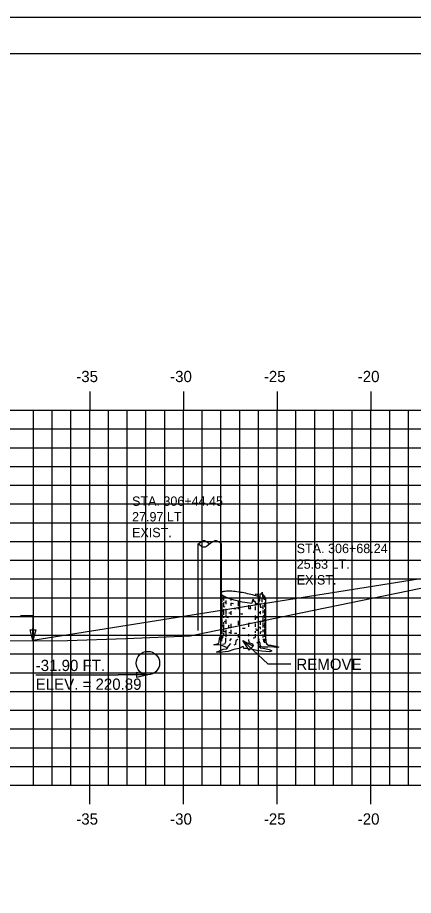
# Model space of a CAD drawing. Extents: x 1137433 to 1137603, y 608981 to 609091.
# Drawn here: x 1137476.8 to 1137497.92, y 609044.46 to 609091.28 of the extents above; entities that cross this region are included whole.
import ezdxf

# ---------------------------------------------------------------- set-up
doc = ezdxf.new("R2010")
doc.units = 0
for name, color, linetype in [('ANNOTATION', 7, 'Continuous'), ('BORDER', 7, 'Continuous'), ('D_Drainage_Culvert', 7, 'Continuous'), ('D_Text_Monospaced', 7, 'Continuous'), ('D_Text_Standard', 7, 'Continuous'), ('H_V ANNOTATION', 7, 'Continuous'), ('MAJOR', 7, 'Continuous'), ('MINOR', 7, 'Continuous'), ('PLOT BOUNDARY', 7, 'Continuous'), ('S_Roadway_Centerline', 7, 'Continuous'), ('S_Trees_Decid_Pay', 7, 'Continuous'), ('S_Utilities_Pole_Power', 7, 'Continuous')]:
    doc.layers.add(name, color=color, linetype=linetype)

msp = doc.modelspace()

# ---------------------------------------------------------------- linework, layer by layer
at = {"layer": 'ANNOTATION'}
for p, q in [((1137498.181, 609061.327), (1137477.623, 609058.046)), ((1137488.823, 609058.049), (1137490.174, 609056.786)), ((1137491.374, 609056.786), (1137490.174, 609056.786))]:
    msp.add_line(p, q, dxfattribs=at)
msp.add_lwpolyline([(1137489.159, 609057.53), (1137488.823, 609058.049), (1137489.364, 609057.749)], close=True, dxfattribs=at)
at = {"layer": 'BORDER'}
msp.add_lwpolyline([(1137440.653, 608984.335), (1137600.653, 608984.335), (1137600.653, 609089.335), (1137440.653, 609089.335)], close=True, dxfattribs=at)
at = {"layer": 'D_Drainage_Culvert'}
msp.add_circle((1137483.753, 609056.85), 0.625, dxfattribs=at)
at = {"layer": 'D_Text_Standard'}
msp.add_line((1137477.771, 609056.225), (1137482.164, 609056.225), dxfattribs=at)
for points in [[(1137477.623, 609058.046), (1137477.633, 609059.372), (1137476.953, 609059.372)], [(1137483.753, 609056.225), (1137482.844, 609056.225), (1137482.164, 609056.225)]]:
    msp.add_lwpolyline(points, dxfattribs=at)
for points in [[(1137477.623, 609058.046), (1137477.482, 609058.629), (1137477.773, 609058.627)], [(1137483.753, 609056.225), (1137483.171, 609056.08), (1137483.171, 609056.371)]]:
    msp.add_lwpolyline(points, close=True, dxfattribs=at)
at = {"layer": 'MAJOR'}
for p, q in [((1137480.653, 609071.337), (1137480.653, 609070.335)), ((1137485.653, 609071.337), (1137485.653, 609070.335)), ((1137490.653, 609071.337), (1137490.653, 609070.335)), ((1137495.653, 609071.337), (1137495.653, 609070.335)), ((1137445.653, 609070.335), (1137585.653, 609070.335)), ((1137445.653, 609070.335), (1137585.653, 609070.335)), ((1137480.653, 609050.335), (1137480.653, 609070.335)), ((1137485.653, 609050.335), (1137485.653, 609070.335)), ((1137490.653, 609050.335), (1137490.653, 609070.335)), ((1137495.653, 609050.335), (1137495.653, 609070.335)), ((1137445.653, 609065.335), (1137585.653, 609065.335)), ((1137445.653, 609060.335), (1137585.653, 609060.335)), ((1137445.653, 609055.335), (1137585.653, 609055.335)), ((1137445.653, 609050.335), (1137585.653, 609050.335)), ((1137445.653, 609050.335), (1137585.653, 609050.335)), ((1137480.653, 609049.333), (1137480.653, 609050.335)), ((1137485.653, 609049.333), (1137485.653, 609050.335)), ((1137490.653, 609049.333), (1137490.653, 609050.335)), ((1137495.653, 609049.333), (1137495.653, 609050.335))]:
    msp.add_line(p, q, dxfattribs=at)
at = {"layer": 'MINOR'}
for p, q in [((1137477.653, 609050.335), (1137477.653, 609070.335)), ((1137478.653, 609050.335), (1137478.653, 609070.335)), ((1137479.653, 609050.335), (1137479.653, 609070.335)), ((1137481.653, 609050.335), (1137481.653, 609070.335)), ((1137482.653, 609050.335), (1137482.653, 609070.335)), ((1137483.653, 609050.335), (1137483.653, 609070.335)), ((1137484.653, 609050.335), (1137484.653, 609070.335)), ((1137486.653, 609050.335), (1137486.653, 609070.335)), ((1137487.653, 609050.335), (1137487.653, 609070.335)), ((1137488.653, 609050.335), (1137488.653, 609070.335)), ((1137489.653, 609050.335), (1137489.653, 609070.335)), ((1137491.653, 609050.335), (1137491.653, 609070.335)), ((1137492.653, 609050.335), (1137492.653, 609070.335)), ((1137493.653, 609050.335), (1137493.653, 609070.335)), ((1137494.653, 609050.335), (1137494.653, 609070.335)), ((1137496.653, 609050.335), (1137496.653, 609070.335)), ((1137497.653, 609050.335), (1137497.653, 609070.335)), ((1137445.653, 609069.335), (1137585.653, 609069.335)), ((1137445.653, 609068.335), (1137585.653, 609068.335)), ((1137445.653, 609067.335), (1137585.653, 609067.335)), ((1137445.653, 609066.335), (1137585.653, 609066.335)), ((1137445.653, 609064.335), (1137585.653, 609064.335)), ((1137445.653, 609063.335), (1137585.653, 609063.335)), ((1137445.653, 609062.335), (1137585.653, 609062.335)), ((1137445.653, 609061.335), (1137585.653, 609061.335)), ((1137445.653, 609059.335), (1137585.653, 609059.335)), ((1137445.653, 609058.335), (1137585.653, 609058.335)), ((1137445.653, 609057.335), (1137585.653, 609057.335)), ((1137445.653, 609056.335), (1137585.653, 609056.335)), ((1137445.653, 609054.335), (1137585.653, 609054.335)), ((1137445.653, 609053.335), (1137585.653, 609053.335)), ((1137445.653, 609052.335), (1137585.653, 609052.335)), ((1137445.653, 609051.335), (1137585.653, 609051.335))]:
    msp.add_line(p, q, dxfattribs=at)
at = {"layer": 'PLOT BOUNDARY'}
msp.add_lwpolyline([(1137432.56, 608981.276), (1137602.56, 608981.276), (1137602.56, 609091.276), (1137432.56, 609091.276)], close=True, dxfattribs=at)
at = {"layer": 'S_Roadway_Centerline'}
msp.add_lwpolyline([(1137445.653, 609057.929), (1137453.384, 609057.836), (1137462.728, 609057.933), (1137472.775, 609058.023), (1137479.462, 609058.055), (1137482.576, 609058.161), (1137486.003, 609058.295), (1137491.397, 609059.425), (1137498.22, 609060.819), (1137499.297, 609060.966), (1137500.585, 609061.068), (1137507.942, 609061.156), (1137511.268, 609061.183), (1137514.305, 609061.154), (1137522.089, 609061.113), (1137524.047, 609060.511), (1137524.139, 609060.485), (1137524.594, 609060.38), (1137530.466, 609059.405), (1137531.069, 609059.477), (1137535.521, 609059.696), (1137539.278, 609059.952)], dxfattribs=at)
at = {"layer": 'S_Trees_Decid_Pay'}
for p, q in [((1137487.699, 609060.482), (1137487.699, 609060.362)), ((1137487.779, 609060.438), (1137487.779, 609060.184)), ((1137487.699, 609060.31), (1137487.699, 609060.096)), ((1137487.699, 609060.051), (1137487.699, 609059.713)), ((1137487.779, 609060.088), (1137487.779, 609059.824)), ((1137487.912, 609060.184), (1137487.912, 609059.993)), ((1137488.184, 609060.271), (1137488.184, 609060.184)), ((1137488.184, 609060.043), (1137488.184, 609059.904)), ((1137488.568, 609060.17), (1137488.568, 609059.89)), ((1137489.113, 609059.933), (1137489.113, 609059.753)), ((1137489.24, 609059.761), (1137489.235, 609059.867)), ((1137489.478, 609060.032), (1137489.478, 609059.913)), ((1137489.478, 609059.861), (1137489.478, 609059.676)), ((1137489.739, 609060.03), (1137489.739, 609059.825)), ((1137489.824, 609060.279), (1137489.824, 609060.104)), ((1137489.888, 609059.933), (1137489.888, 609059.721)), ((1137489.974, 609060.079), (1137489.974, 609059.824)), ((1137487.699, 609059.596), (1137487.699, 609059.235)), ((1137487.779, 609059.727), (1137487.779, 609059.419)), ((1137487.912, 609059.741), (1137487.912, 609059.464)), ((1137487.912, 609059.419), (1137487.912, 609059.31)), ((1137488.184, 609059.618), (1137488.184, 609059.427)), ((1137488.568, 609059.824), (1137488.568, 609059.721)), ((1137489.478, 609059.39), (1137489.478, 609059.161)), ((1137489.739, 609059.618), (1137489.739, 609059.464)), ((1137489.888, 609059.656), (1137489.888, 609059.507)), ((1137489.974, 609059.727), (1137489.974, 609059.258)), ((1137487.699, 609059.198), (1137487.699, 609058.749)), ((1137487.779, 609059.33), (1137487.779, 609059.264)), ((1137487.779, 609059.03), (1137487.779, 609058.932)), ((1137487.912, 609059.175), (1137487.912, 609058.947)), ((1137488.184, 609058.947), (1137488.184, 609058.739)), ((1137488.568, 609059.11), (1137488.568, 609058.889)), ((1137489.113, 609058.975), (1137489.113, 609058.778)), ((1137489.478, 609058.963), (1137489.478, 609058.778)), ((1137489.739, 609059.101), (1137489.739, 609058.881)), ((1137489.888, 609059.33), (1137489.888, 609059.03)), ((1137489.888, 609058.992), (1137489.888, 609058.749)), ((1137489.974, 609059.207), (1137489.974, 609059.073)), ((1137489.974, 609059.015), (1137489.974, 609058.69)), ((1137487.699, 609058.684), (1137487.699, 609058.402)), ((1137487.779, 609058.881), (1137487.779, 609058.521)), ((1137487.779, 609058.469), (1137487.779, 609058.303)), ((1137487.912, 609058.617), (1137487.912, 609058.234)), ((1137488.184, 609058.617), (1137488.184, 609058.418)), ((1137489.478, 609058.543), (1137489.478, 609058.467)), ((1137489.739, 609058.782), (1137489.739, 609058.661)), ((1137489.739, 609058.51), (1137489.739, 609058.411)), ((1137489.888, 609058.638), (1137489.888, 609058.498)), ((1137489.974, 609058.661), (1137489.974, 609058.241)), ((1137488.189, 609058.161), (1137488.109, 609058.029)), ((1137488.568, 609058.389), (1137488.568, 609058.216)), ((1137489.113, 609058.395), (1137489.113, 609058.292)), ((1137489.478, 609058.389), (1137489.478, 609058.216)), ((1137489.888, 609058.366), (1137489.888, 609058.21)), ((1137489.97, 609058.138), (1137489.985, 609058.02))]:
    msp.add_line(p, q, dxfattribs=at)
for points in [[(1137490.024, 609060.353), (1137490.024, 609058.216), (1137490.045, 609058.074), (1137490.05, 609057.948), (1137490.094, 609057.862), (1137490.186, 609057.812), (1137490.322, 609057.812), (1137490.566, 609057.757), (1137490.732, 609057.707), (1137490.59, 609057.677), (1137490.353, 609057.714), (1137490.143, 609057.701), (1137489.882, 609057.707), (1137489.758, 609057.726), (1137489.728, 609057.683), (1137489.665, 609057.726), (1137489.764, 609057.658), (1137489.999, 609057.633), (1137490.23, 609057.572), (1137490.36, 609057.501), (1137490.26, 609057.458), (1137489.839, 609057.477), (1137489.56, 609057.52), (1137489.262, 609057.596), (1137488.976, 609057.633), (1137488.871, 609057.633), (1137488.852, 609057.714), (1137488.784, 609057.72), (1137488.617, 609057.633), (1137488.331, 609057.577), (1137488.033, 609057.47), (1137487.573, 609057.421), (1137487.419, 609057.434), (1137487.761, 609057.584), (1137487.964, 609057.615), (1137487.953, 609057.689), (1137487.693, 609057.788), (1137487.518, 609057.819), (1137487.277, 609057.831), (1137487.475, 609057.868), (1137487.537, 609057.905), (1137487.561, 609057.991), (1137487.573, 609058.161), (1137487.619, 609058.247), (1137487.647, 609058.488), (1137487.647, 609060.574)], [(1137489.646, 609060.392), (1137489.625, 609060.499), (1137489.493, 609060.53), (1137489.485, 609060.442)], [(1137489.668, 609060.026), (1137489.676, 609060.17), (1137489.721, 609060.162), (1137489.735, 609060.537), (1137489.83, 609060.545), (1137489.844, 609060.625), (1137489.882, 609060.287), (1137489.927, 609060.382), (1137489.947, 609060.228), (1137490.024, 609060.353), (1137490.018, 609060.163)], [(1137490.024, 609060.353), (1137489.978, 609060.376), (1137489.956, 609060.442), (1137489.904, 609060.465), (1137489.871, 609060.39)], [(1137489.506, 609060.03), (1137489.47, 609060.133), (1137489.404, 609060.139), (1137489.404, 609060.221), (1137489.33, 609060.228), (1137489.305, 609060.047)], [(1137488.071, 609058.753), (1137488.072, 609058.829), (1137488.08, 609058.896)], [(1137489.616, 609058.661), (1137489.625, 609058.587), (1137489.55, 609058.581), (1137489.536, 609058.698)], [(1137487.697, 609058.329), (1137487.637, 609058.169), (1137487.623, 609058.043), (1137487.631, 609057.946)], [(1137487.755, 609058.249), (1137487.683, 609058.146), (1137487.683, 609058.02)], [(1137487.895, 609058.175), (1137487.895, 609057.969), (1137487.837, 609057.86), (1137487.74, 609057.843)], [(1137488.55, 609058.1), (1137488.447, 609058.049), (1137488.432, 609057.843), (1137488.329, 609057.814)], [(1137489.115, 609058.109), (1137489.132, 609057.955), (1137489.33, 609057.874), (1137489.375, 609057.771)], [(1137489.758, 609057.726), (1137489.739, 609057.905), (1137489.678, 609058.041), (1137489.684, 609058.142)], [(1137489.904, 609058.146), (1137489.911, 609058.02), (1137489.993, 609057.926)], [(1137487.964, 609057.615), (1137488.051, 609057.757), (1137488.183, 609057.899)], [(1137489.567, 609057.973), (1137489.641, 609057.905), (1137489.659, 609057.806), (1137489.665, 609057.726)]]:
    msp.add_lwpolyline(points, dxfattribs=at)
for centre, radius, start, end in [((1137487.693, 609060.574), 0.0467, 169.2221, 180.9043), ((1137487.701, 609060.574), 0.0544, 180.9043, 191.7221), ((1137487.693, 609060.574), 0.0467, 157.54, 169.2221), ((1137487.711, 609060.576), 0.0645, 191.7221, 204.3989), ((1137487.701, 609060.571), 0.0544, 146.7221, 157.54), ((1137487.75, 609060.594), 0.107, 204.3989, 214.2221), ((1137487.709, 609060.565), 0.0645, 134.0453, 146.7221), ((1137487.797, 609060.625), 0.164, 214.2221, 228.4286), ((1137487.739, 609060.534), 0.107, 124.2221, 134.0453), ((1137487.771, 609060.488), 0.164, 110.0157, 124.2221), ((1137488.006, 609060.861), 0.48, 228.4286, 236.7221), ((1137487.879, 609060.191), 0.48, 101.7221, 110.0157), ((1137488.456, 609061.547), 1.299, 236.7221, 252.1387), ((1137488.045, 609059.388), 1.299, 86.3056, 101.7221), ((1137487.734, 609054.572), 6.126, 79.2221, 86.3056), ((1137487.734, 609054.572), 6.126, 72.1387, 79.2221), ((1137489.215, 609059.166), 1.299, 66.6931, 72.1387), ((1137487.701, 609060.247), 0.0554, 191.6815, 202.5), ((1137487.702, 609059.986), 0.0554, 191.6815, 202.5), ((1137487.711, 609060.251), 0.0657, 202.5, 215.1737), ((1137487.711, 609059.99), 0.0657, 202.5, 215.1737), ((1137487.746, 609060.276), 0.109, 215.1737, 225), ((1137487.747, 609060.015), 0.109, 215.1737, 225), ((1137487.787, 609060.317), 0.166, 225, 238.33), ((1137487.788, 609060.056), 0.166, 225, 239.1924), ((1137487.95, 609060.329), 0.484, 239.1924, 242.5838), ((1137488.259, 609061.075), 1.292, 247.5, 251.9171), ((1137488.258, 609061.336), 1.292, 250.9084, 254.4349), ((1137489.936, 609066.141), 6.126, 252.1387, 259.2221), ((1137488.834, 609065.924), 5.916, 263.6913, 265.0485), ((1137489.936, 609066.141), 6.126, 259.2221, 264.0853), ((1137489.936, 609066.141), 6.126, 265.9754, 266.3056), ((1137489.625, 609061.324), 1.299, 266.3056, 271.8711), ((1137489.411, 609061.075), 1.292, 284.7144, 289.3881), ((1137489.883, 609060.056), 0.166, 300.8076, 315), ((1137489.924, 609060.015), 0.109, 315, 324.8263), ((1137489.959, 609059.99), 0.0657, 324.8263, 337.5), ((1137489.969, 609059.986), 0.0554, 337.5, 348.3185), ((1137489.976, 609059.985), 0.0476, 348.3185, 0), ((1137487.702, 609059.465), 0.0554, 191.6815, 202.5), ((1137487.711, 609059.469), 0.0657, 202.5, 215.1737), ((1137487.747, 609059.494), 0.109, 215.1737, 225), ((1137487.788, 609059.535), 0.166, 225, 239.1924), ((1137487.788, 609059.792), 0.166, 238.3999, 239.1924), ((1137487.95, 609060.065), 0.484, 239.1924, 247.5), ((1137487.95, 609059.808), 0.484, 239.1924, 245.3628), ((1137488.259, 609060.811), 1.292, 247.5, 248.1929), ((1137488.259, 609060.811), 1.292, 261.6338, 262.8454), ((1137488.835, 609065.399), 5.916, 262.8454, 263.6816), ((1137488.835, 609065.663), 5.916, 265.1076, 266.4618), ((1137488.835, 609065.399), 5.916, 268.2292, 269.8838), ((1137488.835, 609065.663), 5.916, 272.6957, 273.9224), ((1137489.411, 609060.811), 1.292, 280.7368, 284.7144), ((1137489.411, 609060.811), 1.292, 291.6463, 292.5), ((1137489.72, 609060.065), 0.484, 292.5, 300.8076), ((1137489.72, 609059.808), 0.484, 294.2275, 300.8076), ((1137489.883, 609059.792), 0.166, 300.8076, 302.9622), ((1137489.883, 609059.535), 0.166, 300.8076, 315), ((1137489.924, 609059.494), 0.109, 315, 324.8263), ((1137489.959, 609059.469), 0.0657, 324.8263, 337.5), ((1137489.969, 609059.465), 0.0554, 337.5, 348.3185), ((1137489.976, 609059.464), 0.0476, 348.3185, 0), ((1137487.702, 609059.208), 0.0554, 191.6815, 202.5), ((1137487.702, 609058.942), 0.0554, 191.6815, 202.5), ((1137487.711, 609059.212), 0.0657, 202.5, 215.1737), ((1137487.747, 609059.237), 0.109, 215.1737, 225), ((1137487.788, 609059.277), 0.166, 225, 237.9306), ((1137488.259, 609060.297), 1.292, 249.8999, 254.3895), ((1137488.259, 609060.554), 1.292, 254.3895, 260.7435), ((1137488.835, 609064.885), 5.916, 272.6957, 273.7279), ((1137488.835, 609065.142), 5.916, 276.2405, 277.1546), ((1137489.411, 609060.554), 1.292, 277.1546, 278.1274), ((1137489.411, 609060.297), 1.292, 288.201, 292.5), ((1137489.411, 609060.554), 1.292, 291.5158, 292.5), ((1137489.883, 609059.277), 0.166, 300.8076, 315), ((1137489.924, 609059.237), 0.109, 315, 324.8263), ((1137489.959, 609059.212), 0.0657, 324.8263, 337.5), ((1137489.959, 609058.946), 0.0657, 324.8263, 337.5), ((1137489.969, 609059.208), 0.0554, 337.5, 348.3185), ((1137489.969, 609058.942), 0.0554, 337.5, 348.3185), ((1137489.976, 609059.206), 0.0476, 348.3185, 0), ((1137489.976, 609058.941), 0.0476, 348.3185, 0), ((1137487.702, 609058.671), 0.0554, 191.6815, 202.5), ((1137487.711, 609058.675), 0.0657, 202.5, 215.1737), ((1137487.747, 609058.7), 0.109, 215.1737, 225), ((1137487.788, 609058.74), 0.166, 225, 237.9306), ((1137487.788, 609059.012), 0.166, 237.9306, 239.1924), ((1137487.95, 609059.285), 0.484, 239.1924, 247.5), ((1137488.259, 609059.759), 1.292, 250.8466, 254.3895), ((1137488.259, 609060.031), 1.292, 261.6205, 262.8454), ((1137488.259, 609059.759), 1.292, 261.6338, 262.8454), ((1137488.835, 609064.619), 5.916, 262.8454, 263.6816), ((1137488.835, 609064.347), 5.916, 262.8454, 263.6816), ((1137488.835, 609064.347), 5.916, 265.539, 266.7363), ((1137488.835, 609064.619), 5.916, 269.7243, 270), ((1137488.835, 609064.619), 5.916, 270, 271.0793), ((1137489.411, 609060.031), 1.292, 280.7537, 284.7144), ((1137489.411, 609059.759), 1.292, 284.7144, 288.6336), ((1137489.411, 609060.031), 1.292, 291.6463, 292.5), ((1137489.72, 609059.285), 0.484, 292.5, 300.8076), ((1137489.72, 609059.013), 0.484, 292.5, 297.266), ((1137489.883, 609059.012), 0.166, 300.8076, 315), ((1137489.924, 609058.971), 0.109, 315, 324.8263), ((1137487.95, 609058.756), 0.484, 243.4501, 247.5), ((1137488.25, 609059.506), 1.292, 247.9396, 248.6304), ((1137488.835, 609064.09), 5.916, 275.2344, 276.2169), ((1137489.411, 609059.502), 1.292, 291.6463, 292.5), ((1137489.72, 609058.756), 0.484, 292.5, 300.8076), ((1137489.883, 609058.483), 0.166, 300.8076, 315), ((1137489.924, 609058.442), 0.109, 315, 324.8263), ((1137489.959, 609058.417), 0.0657, 324.8263, 337.5), ((1137489.969, 609058.413), 0.0554, 337.5, 348.3185), ((1137489.976, 609058.412), 0.0476, 348.3185, 0)]:
    msp.add_arc(centre, radius, start, end, dxfattribs=at)
at = {"layer": 'S_Utilities_Pole_Power'}
for p, q in [((1137486.435, 609063.203), (1137486.591, 609063.314)), ((1137486.435, 609058.584), (1137486.438, 609063.203)), ((1137486.591, 609063.092), (1137486.435, 609063.203)), ((1137486.903, 609063.314), (1137487.06, 609063.203)), ((1137487.06, 609063.203), (1137486.903, 609063.092)), ((1137487.216, 609063.314), (1137487.06, 609063.203)), ((1137487.685, 609063.203), (1137487.529, 609063.314)), ((1137487.685, 609058.584), (1137487.688, 609063.203))]:
    msp.add_line(p, q, dxfattribs=at)
for centre, start, end in [((1137486.747, 609063.093), 90, 125.2644), ((1137486.747, 609063.093), 54.7356, 90), ((1137487.372, 609063.093), 90, 125.2644), ((1137487.372, 609063.093), 54.7356, 90), ((1137486.747, 609063.314), 234.7356, 270), ((1137486.747, 609063.314), 270, 305.2644)]:
    msp.add_arc(centre, 0.271, start, end, dxfattribs=at)

# ---------------------------------------------------------------- texts
at = {"layer": 'ANNOTATION'}
msp.add_text('REMOVE', height=0.6, dxfattribs=at).set_placement((1137491.674, 609056.486))
at = {"layer": 'D_Text_Monospaced'}
for s, height, p in [('STA. 306+44.45', 0.49998, (1137482.91, 609065.236)), ('27.97 LT.', 0.5, (1137482.91, 609064.402)), ('EXIST. ', 0.5, (1137482.91, 609063.562)), ('STA. 306+68.24', 0.49998, (1137491.691, 609062.714)), ('25.63 LT.', 0.5, (1137491.691, 609061.88)), ('EXIST. ', 0.5, (1137491.691, 609061.04))]:
    msp.add_text(s, height=height, dxfattribs=at).set_placement(p)
at = {"layer": 'D_Text_Standard'}
for s, p in [('-31.90 FT.', (1137477.771, 609056.425)), ('ELEV. = 220.89', (1137477.771, 609055.425))]:
    msp.add_text(s, height=0.6, dxfattribs=at).set_placement(p)
at = {"layer": 'H_V ANNOTATION'}
for s, p in [('-35', (1137479.933, 609071.835)), ('-30', (1137484.941, 609071.835)), ('-25', (1137489.938, 609071.835)), ('-20', (1137494.946, 609071.835)), ('-35', (1137479.933, 609048.235)), ('-30', (1137484.941, 609048.235)), ('-25', (1137489.938, 609048.235)), ('-20', (1137494.946, 609048.235))]:
    msp.add_text(s, height=0.6, dxfattribs=at).set_placement(p)

doc.saveas('drawing.dxf')
